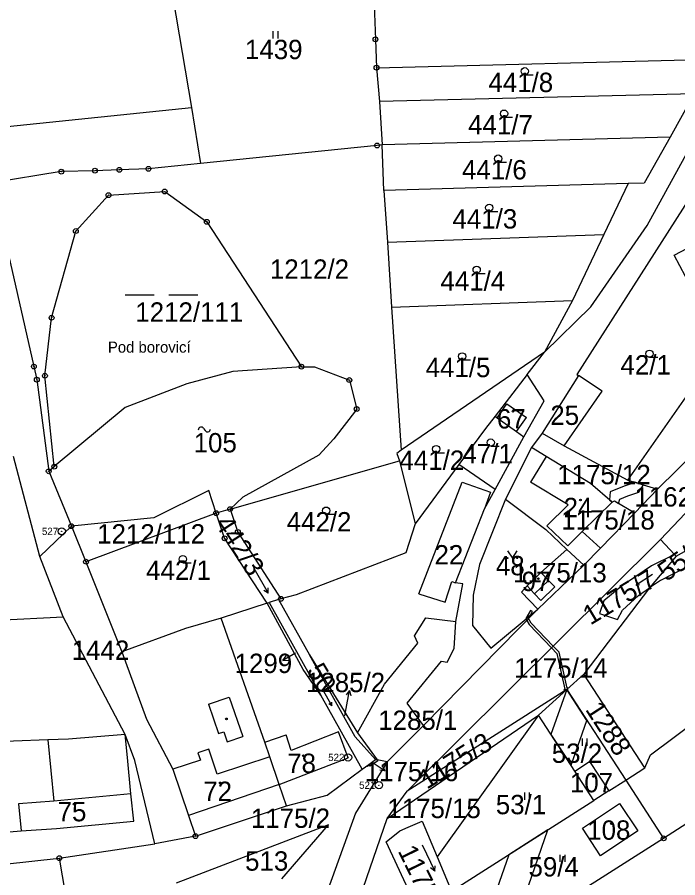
# Model space of a CAD drawing. Extents: x -564516 to -563466, y -1163913 to -1163170.
# Drawn here: x -564413.8 to -564277.2, y -1163494.9 to -1163317 of the extents above; entities that cross this region are included whole.
import ezdxf

# ---------------------------------------------------------------- set-up
doc = ezdxf.new("R2010")
doc.units = 0
for name, color, linetype in [('Hranice parcel', 7, 'Continuous'), ('Parcelní čísla', 7, 'Continuous'), ('Pop  PČ popisy', 7, 'Continuous'), ('Vnitřní kresba', 7, 'Continuous'), ('Věcná břemena k části', 7, 'Continuous'), ('Značky bodu BP', 7, 'Continuous'), ('Značky budov', 7, 'Continuous'), ('Značky kultur', 7, 'Continuous')]:
    doc.layers.add(name, color=color, linetype=linetype)

msp = doc.modelspace()

# ---------------------------------------------------------------- linework, layer by layer
at = {"layer": 'Hranice parcel'}
for p, q in [((-564384.24, -1163297.26), (-564377.75, -1163335.67)), ((-564339.51, -1163327.45), (-564338.9, -1163334.47)), ((-564273.86, -1163332.84), (-564338.9, -1163334.47)), ((-564273.86, -1163332.84), (-564278.79, -1163341.81)), ((-564338.9, -1163334.47), (-564338.36, -1163343.43)), ((-564415.82, -1163339.6), (-564377.75, -1163335.67)), ((-564377.75, -1163335.67), (-564375.89, -1163347.26)), ((-564278.79, -1163341.81), (-564338.36, -1163343.43)), ((-564337.96, -1163352.84), (-564338.36, -1163343.43)), ((-564287.48, -1163351.39), (-564337.96, -1163352.84)), ((-564287.48, -1163351.39), (-564292.5, -1163361.92)), ((-564337.96, -1163352.84), (-564337.26, -1163363.54)), ((-564337.26, -1163363.54), (-564292.5, -1163361.92)), ((-564292.5, -1163361.92), (-564299.02, -1163375.58)), ((-564337.26, -1163363.54), (-564336.38, -1163376.93)), ((-564287.56, -1163412.69), (-564255.92, -1163367.46)), ((-564336.38, -1163376.93), (-564299.02, -1163375.58)), ((-564299.02, -1163375.58), (-564304.77, -1163386.26)), ((-564336.38, -1163376.93), (-564334.4, -1163406.5)), ((-564304.77, -1163386.26), (-564334.4, -1163406.5)), ((-564308.34, -1163390.89), (-564304.77, -1163386.26)), ((-564308.34, -1163390.89), (-564315, -1163399.49)), ((-564297.75, -1163391.1), (-564305.26, -1163403.01)), ((-564281.4, -1163414.57), (-564257.3, -1163390.75)), ((-564314.98, -1163414.67), (-564309.04, -1163403.77)), ((-564305.26, -1163403.01), (-564307.45, -1163405.97)), ((-564305.26, -1163403.01), (-564300.68, -1163405.61)), ((-564307.45, -1163405.97), (-564312.84, -1163416.65)), ((-564300.68, -1163405.61), (-564287.56, -1163412.69)), ((-564409.08, -1163428.48), (-564414.56, -1163407.85)), ((-564407.26, -1163410.87), (-564406.11, -1163409.91)), ((-564369.77, -1163418.69), (-564334.77, -1163408.7)), ((-564334.77, -1163408.7), (-564331.48, -1163421.73)), ((-564322.46, -1163409.5), (-564331.48, -1163421.73)), ((-564314.98, -1163414.67), (-564322.46, -1163409.5)), ((-564407.26, -1163410.87), (-564402.59, -1163422.22)), ((-564287.56, -1163412.69), (-564281.4, -1163414.57)), ((-564269.44, -1163412.98), (-564280.83, -1163424.99)), ((-564372.65, -1163419.52), (-564374.19, -1163414.85)), ((-564281.4, -1163414.57), (-564286.09, -1163419.43)), ((-564367.13, -1163416.23), (-564369.77, -1163418.69)), ((-564369.77, -1163418.69), (-564372.65, -1163419.52)), ((-564372.65, -1163419.52), (-564399.56, -1163429.57)), ((-564286.09, -1163419.43), (-564293.19, -1163426.78)), ((-564409.08, -1163428.48), (-564402.59, -1163422.22)), ((-564402.59, -1163422.22), (-564399.56, -1163429.57)), ((-564333.17, -1163477.01), (-564280.83, -1163424.99)), ((-564280.83, -1163424.99), (-564277.87, -1163428.08)), ((-564305.53, -1163431.79), (-564300.13, -1163427.07)), ((-564300.13, -1163427.07), (-564296.65, -1163430.25)), ((-564296.65, -1163430.25), (-564293.19, -1163426.78)), ((-564277.59, -1163428.4), (-564275.38, -1163427.19)), ((-564404.27, -1163440.99), (-564409.08, -1163428.48)), ((-564399.56, -1163429.57), (-564392.13, -1163448.22)), ((-564277.59, -1163428.4), (-564283.08, -1163434.99)), ((-564277.87, -1163428.08), (-564282.66, -1163430.41)), ((-564277.87, -1163428.08), (-564277.59, -1163428.4)), ((-564296.65, -1163430.25), (-564306.13, -1163439.34)), ((-564305.53, -1163431.79), (-564308.38, -1163434.53)), ((-564283.08, -1163434.99), (-564296.64, -1163452.83)), ((-564285.36, -1163436.53), (-564283.08, -1163434.99)), ((-564280.8, -1163433.44), (-564283.08, -1163434.99)), ((-564362.14, -1163438.16), (-564371.62, -1163441.24)), ((-564362.14, -1163438.16), (-564361.71, -1163438.02)), ((-564359.75, -1163437.39), (-564361.71, -1163438.02)), ((-564361.71, -1163438.02), (-564351.01, -1163457.13)), ((-564359.27, -1163437.24), (-564359.75, -1163437.39)), ((-564359.75, -1163437.39), (-564353.36, -1163448.83)), ((-564306.13, -1163439.34), (-564329.81, -1163463.41)), ((-564463.39, -1163443.69), (-564404.27, -1163440.99)), ((-564391.49, -1163465.3), (-564404.27, -1163440.99)), ((-564353.36, -1163448.83), (-564343.41, -1163464.9)), ((-564296.64, -1163452.83), (-564300.18, -1163456.01)), ((-564284.03, -1163472.2), (-564296.64, -1163452.83)), ((-564300.18, -1163456.01), (-564333.17, -1163477.01)), ((-564306.04, -1163461.28), (-564300.18, -1163456.01)), ((-564300.18, -1163456.01), (-564287.99, -1163474.72)), ((-564342.44, -1163472.44), (-564351.01, -1163457.13)), ((-564337.31, -1163482.64), (-564306.04, -1163461.28)), ((-564306.04, -1163461.28), (-564326.97, -1163490.55)), ((-564298.48, -1163472.87), (-564306.04, -1163461.28)), ((-564282.89, -1163469.47), (-564271.83, -1163461.21)), ((-564329.81, -1163463.41), (-564337.3, -1163470.94)), ((-564343.41, -1163464.9), (-564339.38, -1163470.49)), ((-564341.11, -1163471.45), (-564339.72, -1163470.42)), ((-564339.72, -1163470.42), (-564339.38, -1163470.49)), ((-564337.3, -1163470.94), (-564339.38, -1163470.49)), ((-564339.38, -1163470.49), (-564339.2, -1163470.74)), ((-564284.03, -1163472.2), (-564282.89, -1163469.47)), ((-564342.44, -1163472.44), (-564341.11, -1163471.45)), ((-564340.83, -1163471.82), (-564341.11, -1163471.45)), ((-564339.2, -1163470.74), (-564340.83, -1163471.82)), ((-564287.99, -1163474.72), (-564284.03, -1163472.2)), ((-564294.55, -1163478.9), (-564298.48, -1163472.87)), ((-564291.48, -1163476.95), (-564287.99, -1163474.72)), ((-564287.99, -1163474.72), (-564280.15, -1163486.75)), ((-564337.31, -1163482.64), (-564333.17, -1163477.01)), ((-564291.48, -1163476.95), (-564294.55, -1163478.9)), ((-564323.98, -1163497.65), (-564294.55, -1163478.9)), ((-564376.94, -1163486.28), (-564358.11, -1163480.05)), ((-564347.82, -1163513.14), (-564337.31, -1163482.64)), ((-564412.93, -1163485.19), (-564405.68, -1163484.7)), ((-564330.06, -1163483.22), (-564326.97, -1163490.55)), ((-564274.36, -1163483.08), (-564280.15, -1163486.75)), ((-564429, -1163486.59), (-564412.93, -1163485.19)), ((-564376.94, -1163486.28), (-564385.35, -1163487.87)), ((-564405.08, -1163490.85), (-564385.35, -1163487.87)), ((-564332.5, -1163498.27), (-564337.51, -1163487.49)), ((-564280.15, -1163486.75), (-564304.67, -1163502.3)), ((-564405.08, -1163490.85), (-564403.85, -1163498.15)), ((-564326.97, -1163490.55), (-564323.98, -1163497.65))]:
    msp.add_line(p, q, dxfattribs=at)
for points in [[(-564304.77, -1163386.26), (-564295.23, -1163376.85), (-564283.56, -1163360.04), (-564247.75, -1163294.75)], [(-564340.65, -1163296.46), (-564339.73, -1163321.6), (-564339.51, -1163327.45)], [(-564339.51, -1163327.45), (-564270.01, -1163325.7), (-564273.86, -1163332.84)], [(-564278.79, -1163341.81), (-564284.18, -1163351.3), (-564287.48, -1163351.39)], [(-564338.36, -1163343.43), (-564339.39, -1163343.53), (-564375.89, -1163347.26)], [(-564375.89, -1163347.26), (-564386.66, -1163348.36), (-564392.67, -1163348.57), (-564397.72, -1163348.74), (-564404.66, -1163348.94), (-564419.03, -1163351.27), (-564410.33, -1163389.23), (-564409.72, -1163391.93), (-564407.26, -1163410.87)], [(-564406.11, -1163409.91), (-564408.05, -1163391.13), (-564406.67, -1163379.14), (-564401.67, -1163361.22), (-564394.92, -1163353.8), (-564383.29, -1163353.05), (-564374.57, -1163359.32), (-564355.03, -1163389.25)], [(-564274.65, -1163354.2), (-564298.1, -1163390.87), (-564297.75, -1163391.1)], [(-564277.95, -1163366.22), (-564269.69, -1163361.87), (-564267.9, -1163365.27), (-564267.12, -1163364.86), (-564266.79, -1163365.47), (-564267.58, -1163365.89), (-564266.26, -1163368.4), (-564268.84, -1163369.75), (-564269.94, -1163367.65), (-564275.63, -1163370.64), (-564277.95, -1163366.22)], [(-564355.03, -1163389.25), (-564369.22, -1163390.28), (-564378.74, -1163392.79), (-564391.47, -1163397.67), (-564406.11, -1163409.91)], [(-564355.03, -1163389.25), (-564352.34, -1163389.27), (-564345.12, -1163392.02), (-564343.6, -1163398), (-564348.33, -1163404.16), (-564351.45, -1163407.53), (-564367.13, -1163416.23)], [(-564309.04, -1163403.77), (-564304.87, -1163396.28), (-564308.34, -1163390.89)], [(-564300.68, -1163405.61), (-564292.84, -1163394.33), (-564297.75, -1163391.1)], [(-564315, -1163399.49), (-564316.94, -1163402.01), (-564322.46, -1163409.5)], [(-564315, -1163399.49), (-564314.55, -1163399.81), (-564310.57, -1163402.64), (-564309.04, -1163403.77)], [(-564334.4, -1163406.5), (-564335.29, -1163407.18), (-564334.77, -1163408.7)], [(-564290.77, -1163417.28), (-564295.26, -1163413.39), (-564304.44, -1163407.8), (-564307.45, -1163405.97)], [(-564374.19, -1163414.85), (-564385.53, -1163420.52), (-564402.59, -1163422.22)], [(-564323.13, -1163441.93), (-564321.68, -1163434.14), (-564323.16, -1163433.91), (-564317.21, -1163418.65), (-564314.98, -1163414.67)], [(-564312.84, -1163416.65), (-564318.21, -1163430.13), (-564319.52, -1163436.5), (-564319.69, -1163442.75), (-564315.89, -1163447.44), (-564306.13, -1163439.34)], [(-564312.84, -1163416.65), (-564304.48, -1163422.93), (-564300.13, -1163427.07)], [(-564290.77, -1163417.28), (-564290.33, -1163417), (-564286.09, -1163419.43)], [(-564369.77, -1163418.69), (-564368.18, -1163423.43), (-564359.27, -1163437.24)], [(-564293.19, -1163426.78), (-564296.98, -1163423.34), (-564290.77, -1163417.28)], [(-564362.14, -1163438.16), (-564370.91, -1163424.73), (-564372.65, -1163419.52)], [(-564331.48, -1163421.73), (-564333.44, -1163427.72), (-564356.08, -1163436.39), (-564359.27, -1163437.24)], [(-564266.24, -1163424.28), (-564275.15, -1163430.58), (-564280.8, -1163433.44)], [(-564282.66, -1163430.41), (-564288.94, -1163434.68), (-564292.52, -1163437.68), (-564293.42, -1163440.24), (-564289.69, -1163441.52), (-564288.64, -1163439.6), (-564285.36, -1163436.53)], [(-564308.38, -1163434.53), (-564306.81, -1163436.21), (-564305.52, -1163437.55), (-564302.65, -1163434.78), (-564303.94, -1163433.44), (-564305.53, -1163431.79)], [(-564306.13, -1163439.34), (-564309.54, -1163435.83), (-564308.38, -1163434.53)], [(-564351.01, -1163457.13), (-564354.7, -1163451.84), (-564362.14, -1163438.16)], [(-564371.62, -1163441.24), (-564379.02, -1163443.34), (-564392.13, -1163448.22)], [(-564358.11, -1163480.05), (-564359.63, -1163475.6), (-564361.55, -1163469.86), (-564362.57, -1163466.83), (-564371.62, -1163441.24)], [(-564343.41, -1163464.9), (-564337.83, -1163454.86), (-564330.94, -1163446.42), (-564331.62, -1163444.86), (-564329.33, -1163441.19), (-564323.13, -1163441.93)], [(-564329.81, -1163463.41), (-564333.15, -1163458.81), (-564326.08, -1163450.15), (-564324.88, -1163450.36), (-564323.47, -1163447.53), (-564323.13, -1163441.93)], [(-564392.13, -1163448.22), (-564387.04, -1163462.09), (-564381.6, -1163472.46), (-564378.4, -1163482.02), (-564376.94, -1163486.28)], [(-564339.72, -1163470.42), (-564343.9, -1163465.78), (-564353.36, -1163448.83)], [(-564407.43, -1163466.4), (-564414.53, -1163466.68), (-564430.16, -1163467.25)], [(-564407.43, -1163466.4), (-564406.22, -1163479.07), (-564413.51, -1163479.62), (-564412.93, -1163485.19)], [(-564391.49, -1163465.3), (-564403.17, -1163466.24), (-564407.43, -1163466.4)], [(-564405.68, -1163484.7), (-564389.65, -1163483.16), (-564390.28, -1163477.54), (-564390.95, -1163470.01), (-564391.49, -1163465.3)], [(-564385.35, -1163487.87), (-564389.44, -1163470.62), (-564391.49, -1163465.3)], [(-564337.3, -1163470.94), (-564343.85, -1163481.54), (-564352.25, -1163504.82), (-564360.15, -1163525.07)], [(-564298.48, -1163472.87), (-564295.46, -1163470.87), (-564291.48, -1163476.95)], [(-564358.11, -1163480.05), (-564349.68, -1163477.81), (-564342.44, -1163472.44)], [(-564289.29, -1163479.52), (-564285.5, -1163485.18), (-564293.17, -1163490.33), (-564296.94, -1163484.67), (-564289.29, -1163479.52)], [(-564359.05, -1163495.11), (-564349.44, -1163483.92), (-564380.93, -1163495.99)], [(-564337.51, -1163487.49), (-564334.69, -1163485.22), (-564332.93, -1163484.41), (-564330.06, -1163483.22)], [(-564516.35, -1163486.11), (-564490.44, -1163494.01), (-564475.97, -1163496.01), (-564456, -1163496.4), (-564405.08, -1163490.85)]]:
    msp.add_lwpolyline(points, dxfattribs=at)
at = {"layer": 'Pop  PČ popisy'}
for p, q in [((-564356.22, -1163448.5), (-564358.85, -1163449.96)), ((-564358.85, -1163449.96), (-564358.21, -1163449.03)), ((-564358.85, -1163449.96), (-564357.73, -1163449.91)), ((-564345.11, -1163456.19), (-564345.78, -1163457.08)), ((-564345.63, -1163459.14), (-564345.11, -1163456.19)), ((-564345.11, -1163456.19), (-564344.79, -1163457.26)), ((-564346.04, -1163461.41), (-564345.63, -1163459.14)), ((-564340.2, -1163471.13), (-564337.71, -1163472.81)), ((-564337.71, -1163472.81), (-564338.26, -1163471.83)), ((-564337.71, -1163472.81), (-564338.82, -1163472.66))]:
    msp.add_line(p, q, dxfattribs=at)
at = {"layer": 'Vnitřní kresba'}
for p, q in [((-564314.55, -1163399.81), (-564312.55, -1163396.94)), ((-564312.55, -1163396.94), (-564308.47, -1163399.79)), ((-564310.57, -1163402.64), (-564308.47, -1163399.79)), ((-564304.44, -1163407.8), (-564307.66, -1163413.1)), ((-564330.78, -1163436.17), (-564321.79, -1163413.09)), ((-564321.79, -1163413.09), (-564315.96, -1163415.21)), ((-564299.91, -1163417.82), (-564307.66, -1163413.1)), ((-564315.96, -1163415.21), (-564317.21, -1163418.65)), ((-564304.32, -1163422.12), (-564299.91, -1163417.82)), ((-564304.32, -1163422.12), (-564299.97, -1163426.26)), ((-564299.97, -1163426.26), (-564296.98, -1163423.34)), ((-564325.31, -1163437.92), (-564323.94, -1163433.66)), ((-564323.94, -1163433.66), (-564323.16, -1163433.91)), ((-564306.81, -1163436.21), (-564303.94, -1163433.44)), ((-564330.78, -1163436.17), (-564325.31, -1163437.92)), ((-564374.26, -1163459.04), (-564369.96, -1163457.57)), ((-564369.96, -1163457.57), (-564367.17, -1163465.71)), ((-564374.26, -1163459.04), (-564372.19, -1163465.1)), ((-564372.19, -1163465.1), (-564371.1, -1163464.73)), ((-564371.1, -1163464.73), (-564370.39, -1163466.81)), ((-564347.35, -1163464.76), (-564357.12, -1163468.6)), ((-564345.34, -1163470.12), (-564347.35, -1163464.76)), ((-564370.39, -1163466.81), (-564367.17, -1163465.71)), ((-564362.57, -1163466.83), (-564358.21, -1163465.36)), ((-564357.12, -1163468.6), (-564358.21, -1163465.36)), ((-564374.19, -1163468.29), (-564376.42, -1163469.04)), ((-564372.44, -1163473.51), (-564374.19, -1163468.29)), ((-564375.91, -1163470.55), (-564381.6, -1163472.46)), ((-564376.42, -1163469.04), (-564375.91, -1163470.55)), ((-564361.55, -1163469.86), (-564372.44, -1163473.51)), ((-564359.63, -1163475.6), (-564345.34, -1163470.12)), ((-564359.63, -1163475.6), (-564378.4, -1163482.02)), ((-564390.28, -1163477.54), (-564406.22, -1163479.07))]:
    msp.add_line(p, q, dxfattribs=at)
at = {"layer": 'Věcná břemena k části'}
for points in [[(-564288.31, -1163413.95), (-564291.18, -1163415.14), (-564291.37, -1163416.76), (-564290.77, -1163417.28), (-564290.33, -1163417), (-564289.45, -1163417.51), (-564289.23, -1163416.61), (-564287.57, -1163415.93), (-564285.29, -1163415.18), (-564284.28, -1163413.69), (-564286.39, -1163413.05), (-564286.63, -1163413.4)], [(-564307.7, -1163439.62), (-564308.65, -1163441.31), (-564308.6, -1163441.39), (-564307.69, -1163440.64), (-564307.26, -1163439.86)], [(-564301.74, -1163448.29), (-564302.98, -1163447), (-564307.56, -1163442.24), (-564308.08, -1163441.32), (-564307.69, -1163440.64), (-564308.6, -1163441.39), (-564308.44, -1163441.69), (-564307.96, -1163442.54), (-564303.33, -1163447.35), (-564302.2, -1163448.53), (-564300.58, -1163455.94), (-564300.75, -1163456.03), (-564300.61, -1163456.29), (-564300.18, -1163456.01), (-564299.88, -1163455.74), (-564299.95, -1163455.61), (-564300.12, -1163455.7)], [(-564296.03, -1163462.38), (-564300.18, -1163456.01), (-564303.44, -1163465.27), (-564299.29, -1163471.63)], [(-564311.37, -1163506.14), (-564304.06, -1163484.96), (-564312.18, -1163490.13), (-564318.94, -1163509.62), (-564318.65, -1163510.3)]]:
    msp.add_lwpolyline(points, close=True, dxfattribs=at)
at = {"layer": 'Značky bodu BP'}
for centre, radius in [((-564339.73, -1163321.6), 0.5), ((-564339.73, -1163321.6), 0.0303), ((-564339.51, -1163327.45), 0.5), ((-564339.51, -1163327.45), 0.0303), ((-564339.39, -1163343.53), 0.5), ((-564339.39, -1163343.53), 0.0303), ((-564404.66, -1163348.94), 0.5), ((-564404.66, -1163348.94), 0.0303), ((-564397.72, -1163348.74), 0.5), ((-564397.72, -1163348.74), 0.0303), ((-564392.67, -1163348.57), 0.5), ((-564392.67, -1163348.57), 0.0303), ((-564386.66, -1163348.36), 0.5), ((-564386.66, -1163348.36), 0.0303), ((-564383.29, -1163353.05), 0.5), ((-564383.29, -1163353.05), 0.0303), ((-564394.92, -1163353.8), 0.5), ((-564394.92, -1163353.8), 0.0303), ((-564374.57, -1163359.32), 0.5), ((-564374.57, -1163359.32), 0.0303), ((-564401.67, -1163361.22), 0.5), ((-564401.67, -1163361.22), 0.0303), ((-564406.67, -1163379.14), 0.5), ((-564406.67, -1163379.14), 0.0303), ((-564410.33, -1163389.23), 0.5), ((-564355.03, -1163389.25), 0.5), ((-564410.33, -1163389.23), 0.0303), ((-564355.03, -1163389.25), 0.0303), ((-564409.72, -1163391.93), 0.5), ((-564409.72, -1163391.93), 0.0303), ((-564408.05, -1163391.13), 0.5), ((-564408.05, -1163391.13), 0.0303), ((-564345.12, -1163392.02), 0.5), ((-564345.12, -1163392.02), 0.0303), ((-564343.6, -1163398), 0.5), ((-564343.6, -1163398), 0.0303), ((-564406.11, -1163409.91), 0.5), ((-564406.11, -1163409.91), 0.0303), ((-564407.26, -1163410.87), 0.5), ((-564407.26, -1163410.87), 0.0303), ((-564369.77, -1163418.69), 0.5), ((-564369.77, -1163418.69), 0.0303), ((-564372.65, -1163419.52), 0.5), ((-564372.65, -1163419.52), 0.0303), ((-564404.57, -1163423.29), 0.75), ((-564402.59, -1163422.22), 0.5), ((-564402.59, -1163422.22), 0.0303), ((-564404.57, -1163423.29), 0.03), ((-564370.91, -1163424.73), 0.5), ((-564368.18, -1163423.43), 0.5), ((-564368.18, -1163423.43), 0.0303), ((-564370.91, -1163424.73), 0.0303), ((-564399.56, -1163429.57), 0.5), ((-564399.56, -1163429.57), 0.0303), ((-564359.27, -1163437.24), 0.5), ((-564359.27, -1163437.24), 0.0303), ((-564345.39, -1163470.01), 0.75), ((-564345.39, -1163470.01), 0.03), ((-564339, -1163475.76), 0.75), ((-564339, -1163475.76), 0.03), ((-564376.94, -1163486.28), 0.5), ((-564376.94, -1163486.28), 0.0303), ((-564280.15, -1163486.75), 0.5), ((-564280.15, -1163486.75), 0.0303), ((-564405.08, -1163490.85), 0.5), ((-564405.08, -1163490.85), 0.0303)]:
    msp.add_circle(centre, radius, dxfattribs=at)
at = {"layer": 'Značky budov'}
msp.add_line((-564375.24, -1163402.04), (-564374.94, -1163402.44), dxfattribs=at)
for centre in [(-564300.03, -1163397.74), (-564311.29, -1163398.48), (-564297.34, -1163416.81), (-564323.94, -1163426.58), (-564306.04, -1163433.07), (-564370.53, -1163462.05), (-564354.62, -1163469.68), (-564294.69, -1163473.94), (-564371.81, -1163475.27), (-564402.04, -1163479.67), (-564290.95, -1163483.72)]:
    msp.add_circle(centre, 0.175, dxfattribs=at)
for centre, start, end in [((-564375.75, -1163402.33), 29.2914, 181.2189), ((-564374.43, -1163402.15), 209.2914, 1.2189)]:
    msp.add_arc(centre, 0.588, start, end, dxfattribs=at)
at = {"layer": 'Značky kultur'}
for p, q in [((-564360.85, -1163321.42), (-564360.85, -1163319.92)), ((-564359.85, -1163321.42), (-564359.85, -1163319.92)), ((-564308.86, -1163328.94), (-564307.11, -1163328.94)), ((-564313.14, -1163337.7), (-564311.39, -1163337.7)), ((-564314.36, -1163347), (-564312.61, -1163347)), ((-564316.2, -1163357.15), (-564314.45, -1163357.15)), ((-564318.8, -1163369.97), (-564317.05, -1163369.97)), ((-564391.44, -1163374.4), (-564385.44, -1163374.4)), ((-564382.44, -1163374.4), (-564376.44, -1163374.4)), ((-564321.8, -1163387.87), (-564320.05, -1163387.87)), ((-564283.07, -1163387.32), (-564281.32, -1163387.32)), ((-564315.89, -1163405.69), (-564314.14, -1163405.69)), ((-564327.18, -1163407.03), (-564325.43, -1163407.03)), ((-564349.92, -1163419.76), (-564348.17, -1163419.76)), ((-564379.54, -1163429.77), (-564377.79, -1163429.77)), ((-564364.87, -1163430.88), (-564361.87, -1163436.08)), ((-564282.47, -1163432.19), (-564285.84, -1163434.38)), ((-564361.87, -1163436.08), (-564361.92, -1163434.98)), ((-564285.84, -1163434.38), (-564285.47, -1163433.74)), ((-564285.84, -1163434.38), (-564285.11, -1163434.3)), ((-564361.87, -1163436.08), (-564362.79, -1163435.48)), ((-564350.72, -1163455.87), (-564348.71, -1163459.35)), ((-564348.71, -1163459.35), (-564349.33, -1163458.96)), ((-564348.71, -1163459.35), (-564348.75, -1163458.62)), ((-564296.95, -1163467.59), (-564296.95, -1163466.09)), ((-564295.95, -1163467.59), (-564295.95, -1163466.09)), ((-564308.87, -1163478.76), (-564308.87, -1163477.26)), ((-564307.87, -1163478.76), (-564307.87, -1163477.26)), ((-564330.07, -1163488.11), (-564327.44, -1163493.51)), ((-564301.51, -1163491.62), (-564301.51, -1163490.12)), ((-564300.51, -1163491.62), (-564300.51, -1163490.12)), ((-564327.44, -1163493.51), (-564328.31, -1163492.85)), ((-564327.44, -1163493.51), (-564327.41, -1163492.41))]:
    msp.add_line(p, q, dxfattribs=at)
msp.add_lwpolyline([(-564312.41, -1163427.32), (-564311.41, -1163428.82), (-564310.41, -1163427.32)], dxfattribs=at)
for centre, radius in [((-564308.86, -1163328.19), 0.75), ((-564313.14, -1163336.95), 0.75), ((-564314.36, -1163346.25), 0.75), ((-564316.2, -1163356.4), 0.75), ((-564318.8, -1163369.22), 0.75), ((-564321.8, -1163387.12), 0.75), ((-564283.07, -1163386.57), 0.75), ((-564315.89, -1163404.94), 0.75), ((-564327.18, -1163406.28), 0.75), ((-564349.92, -1163419.01), 0.75), ((-564379.54, -1163429.02), 0.75), ((-564312.41, -1163428.82), 0.1), ((-564310.41, -1163428.82), 0.1)]:
    msp.add_circle(centre, radius, dxfattribs=at)

# ---------------------------------------------------------------- texts
at = {"layer": 'Parcelní čísla'}
for s, p in [('1439', (-564366.69, -1163325.69)), ('441/8', (-564316.37, -1163332.49)), ('441/7', (-564320.57, -1163341.25)), ('441/6', (-564321.84, -1163350.55)), ('441/3', (-564323.8, -1163360.7)), ('1212/2', (-564361.54, -1163371.08)), ('441/4', (-564326.28, -1163373.52)), ('1212/111', (-564389.36, -1163379.96)), ('42/1', (-564289.07, -1163390.87)), ('441/5', (-564329.35, -1163391.42)), ('25', (-564303.57, -1163401.29)), ('67', (-564314.61, -1163402.03)), ('105', (-564377.3, -1163406.97)), ('441/2', (-564334.76, -1163410.58)), ('47/1', (-564321.74, -1163409.24)), ('1175/12', (-564302.14, -1163413.55)), ('1162/1', (-564286.18, -1163418.16)), ('24', (-564300.82, -1163420.36)), ('1175/18', (-564301.32, -1163422.92)), ('442/2', (-564358.07, -1163423.31)), ('1212/112', (-564397.25, -1163425.81)), ('22', (-564327.52, -1163430.13)), ('442/1', (-564387.12, -1163433.32)), ('48', (-564314.82, -1163432.37)), ('1175/13', (-564311.25, -1163433.84)), ('97', (-564309.5, -1163435.63)), ('1442', (-564402.51, -1163449.86)), ('1299', (-564368.84, -1163452.57)), ('1175/14', (-564311.07, -1163453.53)), ('1285/2', (-564354.09, -1163456.52)), ('1285/1', (-564339.15, -1163464.32)), ('53/2', (-564303.27, -1163471.14)), ('78', (-564357.97, -1163473.23)), ('1175/16', (-564341.94, -1163474.93)), ('107', (-564299.52, -1163477.23)), ('72', (-564375.32, -1163479.02)), ('53/1', (-564314.84, -1163481.76)), ('75', (-564405.43, -1163483.22)), ('1175/15', (-564337.27, -1163482.56)), ('1175/2', (-564365.46, -1163484.58)), ('108', (-564295.95, -1163487.03)), ('513', (-564366.67, -1163493.42)), ('59/4', (-564308.08, -1163494.62))]:
    msp.add_text(s, height=4, dxfattribs=at).set_placement(p)
for s, rotation, p in [('442/3', 303, (-564373.08, -1163421.65)), ('55/2', 35, (-564279.6, -1163433.79)), ('1175/7', 31, (-564295.3, -1163442.77)), ('50', 301, (-564354.07, -1163452.05)), ('1288', 303, (-564296.45, -1163460.1)), ('1175/3', 32, (-564329.09, -1163476.7)), ('1175/17', 296, (-564335.16, -1163489.33))]:
    msp.add_text(s, height=4, rotation=rotation, dxfattribs=at).set_placement(p)
at = {"layer": 'Pop  PČ popisy'}
msp.add_text('Pod borovicí', height=2.3, dxfattribs=at).set_placement((-564395.03, -1163386.36))
at = {"layer": 'Značky bodu BP'}
for s, p in [('527', (-564408.67, -1163424.04)), ('522', (-564349.49, -1163470.76)), ('521', (-564343.1, -1163476.51))]:
    msp.add_text(s, height=1.5, dxfattribs=at).set_placement(p)

doc.saveas('drawing.dxf')
